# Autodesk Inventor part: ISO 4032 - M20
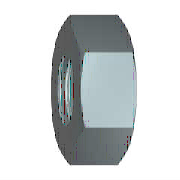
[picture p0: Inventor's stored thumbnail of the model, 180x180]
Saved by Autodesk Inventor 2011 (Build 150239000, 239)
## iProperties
IsCustomPart: 0
Created: 2009-02
Part Number: ISO 4032 - M20
Material: Stainless Steel, 440C
Description: Hexagon nuts, style 1 - Product grades A and B
Document SubType Name: Modeling
Standard: ISO 4032
Designer: V.de Jong
Standard Revision: Third edition 1999-08-15
Standards Organization: ISO
Language: en-US
Size Designation: M20
Categories: <MemberInstance><Categories><Category DisplayName="Fasteners" InternalName="e4da775c-781d-43d5-af7c-5136215cf5a6" Mnemonic="FSTN"><Category DisplayName="Nuts" I
Density: 7.75 g/cm^3
Mass: 73.7481 g
Surface Area: 36.9853 cm^2
Volume: 9.51589 cm^3
Author: V.de Jong
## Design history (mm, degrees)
body "Solid1"
workaxis "Work Axis1"
workplane "Work Plane1"
sketch "Sketch1"
  geometry: L1 (-17.321, 0)-(-8.66, 15); L2 (-8.66, 15)-(8.66, 15); L3 (8.66, 15)-(17.321, 0); L4 (17.321, 0)-(8.66, -15); L5 (8.66, -15)-(-8.66, -15); L6 (-8.66, -15)-(-17.321, 0); 2 further points
  constraints: 12 end point, 1 coincident, 1 horizontal, 11 other
  dimensions: "d0" = 34.64102 distance of L3.end L1.start (= 1.1547 x SW)
extrude "Body" new body sketch "Sketch1" distance "d1" = 18 (= KOH); taper "d2" = 0 deg
revolve "Chamfer1" stored, may be unused: angle "d7" = 90 deg
sketch "Sketch3"
  geometry: 4 further points
  constraints: 1 coincident, 1 other
hole "Thread" sketch "Sketch3" diameter "d25" = 17.294; stored, may be unused: countersink angle "d29" = 82 deg, drill point angle "d31" = 118 deg; dims "d26" = 6, "d27" = 4, "d28" = 2, "d30" = 8
chamfer "Chamfer2" distance "d8" = 1.35316 (= -0.5 x GD1 + 0.5 x NND); stored, may be unused: angle "d9" = 30 deg, second distance "d40" = 1.35316 (= -0.5 x GD1 + 0.5 x NND)
chamfer "Chamfer3" distance "d10" = 1.35316 (= -0.5 x GD1 + 0.5 x NND); stored, may be unused: angle "d11" = 30 deg, second distance "d41" = 1.35316 (= -0.5 x GD1 + 0.5 x NND)
sketch "Sketch2"
  geometry: L1 (0, 8.66)-(0, 17.321) reference; L2 (0, 17.321)-(18, 17.321) reference; L3 (18, 8.66)-(18, 17.321) reference; L4 (-3.6, 0)-(21.6, 0) reference; L5 (2.004, 17.321)-(0, 13.85); L6 (15.996, 17.321)-(18, 13.85)
  constraints: 4 end point, 4 point on line
  dimensions: "d3" = 30 deg angle of L1 L5 (= ANG1); "d4" = 30 deg angle of L3 L6 (= ANG2); "d5" = 27.7 diameter of L5.end L4 (= SW0); "d6" = 27.7 diameter of L6.end L4 (= SW01)
other parameters: "ANG1" = 30 deg [user parameter; used in 1 equation term], "ANG2" = 30 deg [user parameter; used in 1 equation term], "KOH" = 18 [user parameter; used in 1 equation term], "SW0" = 27.7 [user parameter; used in 2 equation terms], "SW01" = 27.7 (= SW0) [user parameter; used in 1 equation term], "GD1" = 17.29367 (computed from THREADDIA, PTC, TOA) [user parameter; used in 4 equation terms], "d13" = 0, "d14" = 0, "d39" = 0, "d42" = 0, "GUL" = 1.35317 (= 0.541266 x PTC) [user parameter], "TPU" = 4 (computed from PTC) [user parameter], "TOA" = 30 deg [user parameter; used in 1 equation term], "PTC" = 2.5 [user parameter; used in 4 equation terms], "E0" = 34.65 (= 1.155 x SW) [user parameter], "GAL" = 1.35317 (= 0.541266 x PTC) [user parameter]
